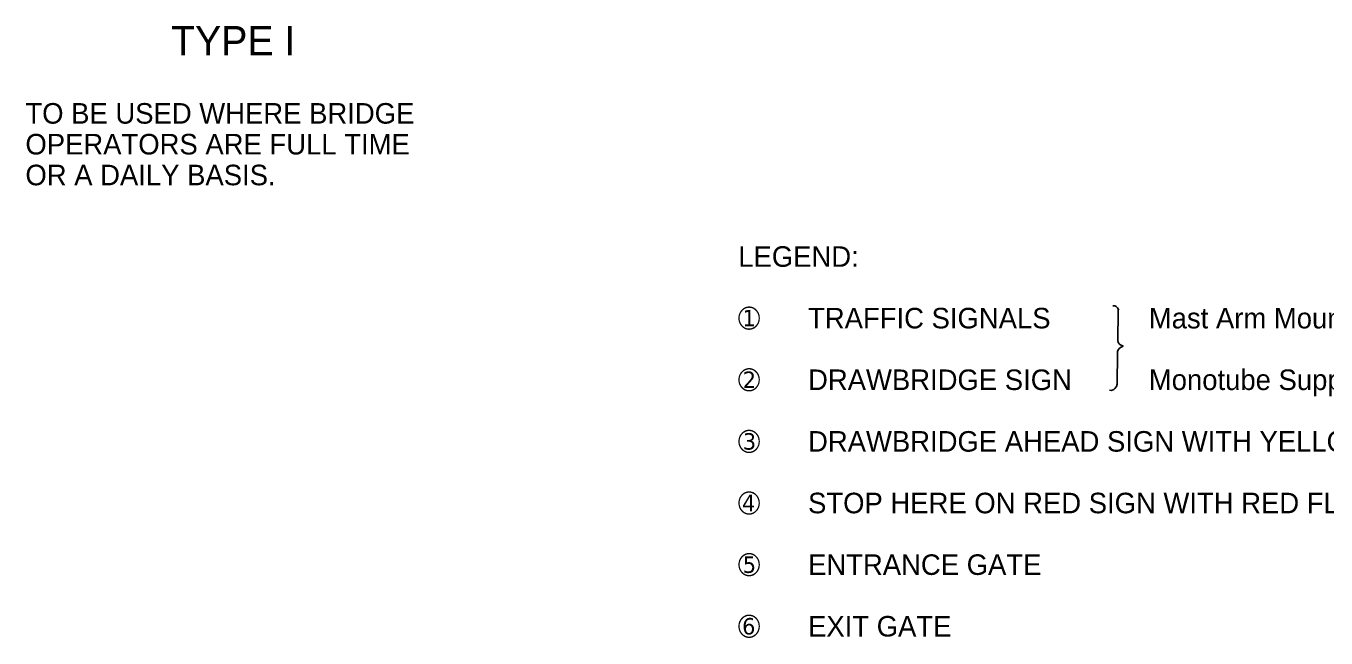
# Model space of a CAD drawing. Extents: x 10000 to 10825, y 10000 to 10530.
# Drawn here: x 10184.1 to 10405.7, y 10255.9 to 10360.2 of the extents above; entities that cross this region are included whole.
import ezdxf

# ---------------------------------------------------------------- set-up
doc = ezdxf.new("R2010")
doc.units = 0
doc.layers.add('Symbols', color=7, linetype='Continuous')
doc.layers.add('TextStructures', color=7, linetype='Continuous')

msp = doc.modelspace()

# ---------------------------------------------------------------- linework, layer by layer
at = {"layer": 'Symbols'}
for points in [[(10370.32, 10312.02), (10370.34, 10311.51), (10370.26, 10306.68), (10370.3, 10306.3), (10370.57, 10305.95), (10370.91, 10305.74), (10371.16, 10305.66), (10370.81, 10305.48), (10370.52, 10305.3), (10370.35, 10305.09), (10370.26, 10304.91), (10370.2, 10304.76), (10370.19, 10304.48), (10370.12, 10299.19), (10370.01, 10298.8), (10369.76, 10298.46), (10369.56, 10298.27), (10369.31, 10298.17), (10369.11, 10298.11), (10368.86, 10298.13)], [(10370.42, 10311.81), (10370.32, 10312.02), (10370.21, 10312.2), (10369.99, 10312.39), (10369.76, 10312.51), (10369.6, 10312.54), (10369.4, 10312.54)]]:
    msp.add_lwpolyline(points, dxfattribs=at)

# ---------------------------------------------------------------- texts
at = {"layer": 'TextStructures'}
for s, height, p in [('TYPE I', 5, (10208.84, 10355.2)), ('TO BE USED WHERE BRIDGE', 3.5, (10184, 10343.57)), ('OPERATORS ARE FULL TIME', 3.5, (10184, 10338.32)), ('OR A DAILY BASIS.', 3.5, (10184, 10333.07))]:
    msp.add_text(s, height=height, rotation=0.0007, dxfattribs=at).set_placement(p)
for s, p in [('LEGEND:', (10305.54, 10319.18)), ('➀', (10305.54, 10308.68)), ('TRAFFIC SIGNALS', (10317.44, 10308.68)), ('Mast Arm Mounted (Off Bridge)', (10375.54, 10308.68)), ('➁', (10305.54, 10298.18)), ('DRAWBRIDGE SIGN', (10317.44, 10298.18)), ('Monotube Support Mounted (On Bridge)', (10375.54, 10298.18)), ('➂', (10305.54, 10287.68)), ('DRAWBRIDGE AHEAD SIGN WITH YELLOW FLASHING BEACON', (10317.44, 10287.68)), ('➃', (10305.54, 10277.18)), ('STOP HERE ON RED SIGN WITH RED FLASHING BEACONS', (10317.44, 10277.18)), ('➄', (10305.54, 10266.68)), ('ENTRANCE GATE', (10317.44, 10266.68)), ('➅', (10305.54, 10256.18)), ('EXIT GATE', (10317.44, 10256.18))]:
    msp.add_text(s, height=3.5, dxfattribs=at).set_placement(p)

doc.saveas('drawing.dxf')
